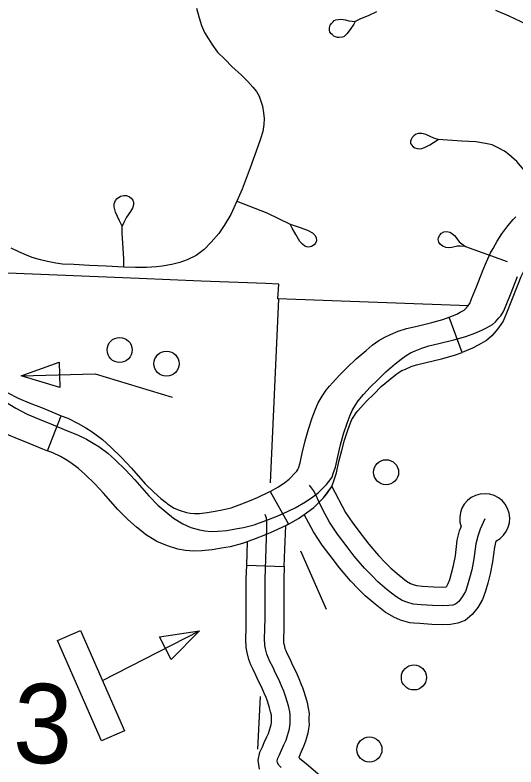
# Model space of a CAD drawing. Extents: x 653372 to 905732, y 627442 to 787275.
# Drawn here: x 658291 to 660290, y 771003 to 774006 of the extents above; entities that cross this region are included whole.
import ezdxf

# ---------------------------------------------------------------- set-up
doc = ezdxf.new("R2010")
doc.units = 0
for name, color, linetype in [('31', 7, 'Continuous'), ('33', 7, 'Continuous'), ('4', 7, 'Continuous'), ('56', 7, 'Continuous'), ('6', 7, 'Continuous')]:
    doc.layers.add(name, color=color, linetype=linetype)

msp = doc.modelspace()

# ---------------------------------------------------------------- linework, layer by layer
at = {"layer": '31'}
for p, q in [((660074.9, 772658.5), (660023, 772799.2)), ((660023, 772799.2), (660023, 772799.2)), ((658420.9, 772265.5), (658475.1, 772405.4)), ((658475.1, 772405.4), (658475.1, 772405.4)), ((659308.4, 772102.8), (659382.7, 771972.5)), ((659215.3, 771808.5), (659365.2, 771803.5))]:
    msp.add_line(p, q, dxfattribs=at)
for points in [[(660023, 772799.2), (660029.7, 772801.7), (660053.3, 772811.3), (660067.6, 772818.7), (660082.9, 772827.3), (660085.2, 772829.5), (660096.6, 772842.3), (660100.6, 772846.9), (660105.2, 772854), (660112.7, 772872), (660132, 772920.1), (660157.6, 772985.9), (660171.7, 773019.9), (660188.5, 773056.1), (660198.5, 773073.8), (660214.2, 773102.8), (660232.8, 773131.9), (660257.5, 773163.2), (660278.4, 773189), (660289.8, 773200)], [(660394.2, 773092.4), (660389.2, 773087.6), (660374.7, 773069.6), (660355.1, 773044.7), (660343.5, 773026.7), (660329.8, 773001.2), (660322, 772987.4), (660309, 772959.5), (660296.7, 772929.9), (660271.5, 772865.1), (660251.6, 772815.2), (660238.4, 772783.7), (660220.7, 772756.3), (660209.2, 772743.2), (660193, 772725), (660172.3, 772705.4), (660138.9, 772686.7), (660116.3, 772675), (660083.9, 772661.8), (660074.9, 772658.5)], [(659170.3, 771953.5), (659201.9, 771959), (659244.8, 771969.9), (659291.2, 771987.2), (659330.5, 772002), (659358, 772014.2), (659408.7, 772038), (659450.4, 772061.8), (659479.3, 772081.7), (659502.2, 772098.6), (659534.2, 772131.1), (659543.4, 772142.2), (659555.7, 772160.5), (659560.9, 772174.7), (659570, 772200.7), (659578.7, 772243.1), (659590.2, 772289.1), (659602.2, 772333), (659616.2, 772375.2), (659627.8, 772407.4), (659635.9, 772426.8), (659647.7, 772446.7), (659660.5, 772465.5), (659681.5, 772490), (659708.5, 772519), (659738.1, 772548.7), (659770.5, 772580.8), (659808.2, 772612.2), (659831.2, 772631.7), (659851.3, 772646), (659869.2, 772656.2), (659887, 772664.2), (659914.4, 772675.6), (659941.8, 772684.4), (659982.1, 772693.8), (660042.2, 772708.5), (660089.2, 772721.8), (660125.3, 772735.1), (660153.3, 772746.5), (660171.7, 772756.1), (660196.1, 772769.8), (660207.6, 772780.6), (660221.4, 772796.2), (660229.1, 772805), (660240.3, 772822.3), (660250.6, 772847), (660270.2, 772896), (660295.6, 772961.3)], [(659545.6, 772523.2), (659557.1, 772536.5), (659585.9, 772567.6), (659616.7, 772598.4), (659651.6, 772632.9), (659691.4, 772666.1), (659716.6, 772687.5), (659742.5, 772706), (659766.8, 772719.7), (659788.7, 772729.6), (659820, 772742.6), (659853.3, 772753.3), (659896.1, 772763.3), (659954.6, 772777.6), (659997.5, 772789.8), (660023, 772799.2)], [(658020.9, 772648.7), (658073.4, 772618.9), (658138.1, 772580.4), (658185.2, 772548.8), (658226.4, 772520.3), (658262.7, 772496.9), (658303.2, 772476.1), (658347.3, 772457.3), (658402.9, 772435), (658456.2, 772412.7), (658475.1, 772405.4)], [(659659.3, 772425.4), (659668.9, 772436.6), (659694, 772463.5), (659722.5, 772492.1), (659752.5, 772521.8), (659788, 772551.4), (659808.8, 772569.1), (659823.1, 772579.3), (659834.6, 772585.7), (659848.4, 772591.9), (659871.8, 772601.7), (659893.4, 772608.6), (659931.1, 772617.5), (659992.9, 772632.6), (660043.9, 772647), (660074.9, 772658.5)], [(657947, 772518.2), (657998.1, 772489.2), (658058, 772453.6), (658100.7, 772424.9), (658143, 772395.6), (658187.6, 772366.9), (658239.5, 772340.1), (658290.1, 772318.7), (658346.1, 772296.2), (658400.2, 772273.6), (658420.9, 772265.5)], [(659308.4, 772102.8), (659342, 772122), (659367.2, 772139.4), (659384.4, 772152.1), (659410.1, 772178.1), (659414.8, 772183.7), (659419.9, 772191.3), (659421.8, 772196.5), (659429, 772217.2), (659437.1, 772256.3), (659449.1, 772304.7), (659461.9, 772351.3), (659476.9, 772396.4), (659489.4, 772431), (659500.1, 772457), (659515.9, 772483.6), (659532.4, 772507.8), (659545.6, 772523.2)], [(658253.2, 772461.3), (658293.7, 772435.3), (658339.8, 772411.5), (658387.2, 772391.4), (658443, 772369), (658496.7, 772346.6), (658539.9, 772329.8), (658575.6, 772312.2), (658602.8, 772296.5), (658624.8, 772282.5), (658660.7, 772256.4), (658690.3, 772228.8), (658731.2, 772189.8), (658768.3, 772149.2), (658824.5, 772085.7), (658861.2, 772048.9), (658892.4, 772021.3), (658923.8, 771996.1), (658959.9, 771973.7), (658993, 771959.4), (659026.3, 771949.3), (659048.6, 771945.5), (659073.5, 771943.6), (659100.2, 771943.9), (659136, 771947.6), (659170.3, 771953.5)], [(659382.7, 771972.5), (659421.9, 771994.9), (659454.4, 772017.3), (659482.9, 772038.4), (659521.4, 772077.3), (659535.1, 772093.8), (659554.5, 772122.7), (659563.1, 772146), (659573.9, 772177.3), (659583.3, 772223), (659594.3, 772266.7), (659605.5, 772307.8), (659618.6, 772347.2), (659629.3, 772376.9), (659634.7, 772389.8), (659642.5, 772403), (659651.6, 772416.4), (659659.4, 772425.4)], [(658475.1, 772405.4), (658501.6, 772395.1), (658542.4, 772375), (658573.2, 772357.2), (658598.5, 772341.1), (658640, 772310.9), (658673.3, 772280), (658716.3, 772238.9), (658755.6, 772196), (658810.7, 772133.7), (658844.2, 772100.1), (658872.2, 772075.2), (658894.9, 772057.1)], [(658801, 771940.1), (658775.5, 771960.5), (658741.3, 771990.9), (658701.3, 772030.9), (658644.1, 772095.6), (658609.1, 772133.8), (658570.3, 772170.9), (658544.5, 772195), (658514, 772217.1), (658495.4, 772228.9), (658471.7, 772242.6), (658441.2, 772257.7), (658420.9, 772265.5)], [(659881.7, 771577.6), (659865.9, 771579), (659829.7, 771589.4), (659802.3, 771600.6), (659767.8, 771621), (659728.2, 771652.6), (659687.9, 771686.7), (659662, 771713), (659629.4, 771746.3), (659586, 771798.2), (659556.5, 771836.5), (659516.9, 771888.7), (659481.4, 771941.9), (659444.7, 772010.6), (659482.9, 772038.4), (659521.4, 772077.3), (659554.7, 772123.1)], [(660165.2, 771994.2), (660146.8, 771952.2), (660137.1, 771924.1), (660129.7, 771894.2), (660122, 771834.1), (660113.6, 771790.6), (660104.9, 771756.6), (660096.9, 771728.5), (660087.9, 771703.6), (660075.5, 771682.1), (660061.3, 771664.2), (660048.6, 771653.3), (660038.4, 771649.5), (660021.8, 771647), (659996.4, 771646), (659957.4, 771647.2), (659911.4, 771650.3), (659879.6, 771653.1), (659854.4, 771660.3), (659835.7, 771668), (659810.4, 771682.9), (659775.8, 771710.6), (659738.9, 771741.8), (659715.4, 771765.6), (659685, 771796.6), (659644.6, 771845.1), (659616.1, 771882), (659578, 771932.2), (659545.8, 771980.5), (659519.5, 772029.7), (659503.4, 772062.7), (659490.6, 772089.7), (659481.7, 772107.1), (659465.7, 772127.7)], [(659554.7, 772123.1), (659610.2, 772019.1), (659639.2, 771975.8), (659675.7, 771927.6), (659703.1, 771892.1), (659740.7, 771847), (659768.9, 771818.2), (659789.9, 771796.9), (659823.5, 771768.5), (659853.1, 771744.8), (659869.2, 771735.3), (659879.1, 771731.3), (659893.3, 771727.2), (659894.5, 771727.1)], [(658894.9, 772057.1), (658898.7, 772054), (658926.2, 772036.9), (658950.3, 772026.5), (658975.1, 772019), (658989.2, 772016.6), (659007.4, 772015.2), (659027.4, 772015.4), (659057.3, 772018.5), (659089.1, 772024), (659117.7, 772029), (659153.9, 772038.2), (659196.4, 772054), (659233.6, 772068), (659258.3, 772079), (659305.6, 772101.2), (659308.4, 772102.8)], [(659353.3, 771000.3), (659343.7, 771010.5), (659338.2, 771019.6), (659337.1, 771027.7), (659339.2, 771038), (659345.9, 771051.7), (659353.6, 771069.3), (659363.7, 771091.5), (659372.3, 771110.5), (659377.8, 771128.3), (659381.7, 771141.2), (659385.8, 771155), (659387.9, 771167), (659389.1, 771176), (659388.9, 771185.8), (659388.8, 771198.4), (659389.2, 771211.4), (659387.4, 771223.6), (659383.4, 771242.1), (659377.7, 771260.8), (659370.4, 771285.3), (659362.9, 771306.1), (659354.6, 771327), (659343.2, 771352.5), (659330.5, 771377.5), (659319.6, 771402.1), (659308.2, 771424.4), (659301.5, 771439.4), (659296.1, 771453.9), (659290.9, 771475.2), (659288.2, 771489.6), (659286.6, 771513.9), (659287.9, 771554.8), (659288.7, 771598.8), (659288.6, 771654.9), (659288.4, 771706), (659288.5, 771753.1), (659292.6, 771874.8), (659295.5, 771957.7), (659296.3, 771984.1), (659294.9, 771996.7), (659289.5, 772010.8)], [(659382.7, 771972.5), (659374.8, 771968), (659320.6, 771942.6), (659290.5, 771929.2), (659249, 771913.6), (659198.8, 771894.8), (659149.1, 771882.2), (659114.5, 771876.2), (659077.8, 771869.9), (659036, 771865.5), (659002.7, 771865.2), (658970.9, 771867.5), (658940.5, 771872.8), (658898.7, 771885.4), (658856.6, 771903.6), (658811.9, 771931.3), (658801, 771940.1)], [(659365.2, 771803.5), (659367.5, 771872.2), (659370.8, 771966.1)], [(659894.5, 771727.1), (659917.2, 771725.1), (659961.1, 771722.1), (659996, 771721.1), (660011.2, 771721.7), (660013.3, 771724.3), (660019.7, 771735.4), (660025.5, 771751.4), (660032.4, 771776.1), (660040.4, 771807), (660047.9, 771846), (660055.8, 771908), (660065.1, 771945.4), (660070.7, 771961.5)], [(659215.3, 771808.5), (659218.4, 771902.2)], [(660209.5, 771904.5), (660203.5, 771880.3), (660196.1, 771822.2), (660186.8, 771774.2), (660177.3, 771737.1), (660168.4, 771705.5), (660156.2, 771671.7), (660137.7, 771639.8), (660115.6, 771611.9), (660087.3, 771587.8), (660057.4, 771576.5), (660028.8, 771572.2), (659996.7, 771571), (659953.7, 771572.3), (659905.7, 771575.6), (659881.7, 771577.6)], [(659296.5, 771269), (659292.8, 771279.6), (659285.5, 771297.8), (659275.5, 771320.2), (659262.8, 771345.3), (659251.9, 771369.7), (659240.5, 771392), (659232, 771411), (659224.2, 771431.9), (659217.5, 771459.4), (659213.6, 771480.4), (659211.6, 771512.7), (659212.9, 771556.7), (659213.7, 771599.4), (659213.6, 771654.6), (659213.4, 771705.9), (659213.5, 771754.4), (659215.3, 771808.5)], [(659365.2, 771803.5), (659363.4, 771751.8), (659363.4, 771706.1), (659363.6, 771655.1), (659363.8, 771598.1), (659362.9, 771553), (659361.7, 771515.1), (659362.7, 771498.9), (659364.2, 771491), (659367.9, 771476), (659370.9, 771467.9), (659375.8, 771456.9), (659387.3, 771434.5), (659398.3, 771409.8), (659411, 771384.7), (659423.7, 771356.2), (659433.1, 771332.7), (659437.8, 771319.5)], [(659437.8, 771319.5), (659441.7, 771308.7), (659449.5, 771282.5), (659456.1, 771260.8), (659461.2, 771237.1), (659464.4, 771216), (659463.9, 771197.5), (659463.9, 771186.6), (659464.1, 771171.7), (659462, 771155.6), (659458.9, 771137.9), (659453.6, 771119.7), (659449.5, 771106.2), (659442.6, 771083.9), (659431.9, 771060.4), (659422.9, 771040.5), (659425.5, 771038.4), (659454.4, 771015.5), (659499.1, 770976.1), (659527.5, 770947.9), (659566.6, 770908.2), (659619.9, 770852.2)], [(659266, 770994), (659261, 771030.3), (659267.6, 771062.3), (659277.8, 771083.1), (659285.1, 771099.9), (659295.4, 771122.5), (659302, 771137.1), (659306.1, 771150.4), (659309.9, 771162.7), (659312.6, 771172.1), (659313.8, 771178.5), (659314, 771180.2), (659313.9, 771185), (659313.8, 771199.3), (659314.1, 771206.8), (659313.6, 771210), (659310.7, 771223.3), (659305.9, 771239.1), (659299.1, 771261.9), (659296.5, 771269)]]:
    msp.add_lwpolyline(points, dxfattribs=at)
msp.add_arc((660165.2, 771994.2), 100, 296.308, 199.0581, dxfattribs=at)
at = {"layer": '33'}
for points in [[(659015.4, 774032.7), (659025.4, 773994.8), (659035.1, 773964.1), (659047.1, 773936.1), (659062.2, 773910.5), (659076.6, 773889.2), (659099.1, 773857.4), (659129.9, 773827.8), (659156, 773800), (659194.2, 773765.4), (659219.2, 773740.1), (659239.7, 773717.2), (659253.8, 773700.3), (659265.5, 773681.2), (659272, 773661.7), (659278.4, 773641.9), (659282.3, 773615.4), (659284.6, 773593), (659283.3, 773568.4), (659279.5, 773541), (659271, 773511.4), (659260.1, 773480), (659228.8, 773394.8), (659197, 773310.5), (659175.6, 773262.5), (659151.7, 773209.3), (659125.8, 773164.9), (659103.7, 773132.7), (659073.9, 773097.9), (659045, 773069.4), (659013.2, 773045.1), (658978, 773027.4), (658949, 773017.2), (658916.2, 773008.8), (658878.5, 773002.9), (658855.6, 772999.5), (658815.1, 772997.8), (658771.7, 772997.9), (658724.8, 772998.7), (658654, 773002.6), (658587.9, 773005.8), (658525.3, 773008.8), (658479.6, 773010.8), (658453.2, 773014.5), (658420.6, 773021.9), (658392.1, 773028.1), (658359.5, 773037.2)], [(659733.2, 774018.6), (659700.5, 774002.8), (659670, 773990), (659648.8, 773980.2)], [(660650.4, 773748.4), (660618.5, 773755.6), (660592.2, 773764.4), (660575.3, 773775), (660539.5, 773799.7), (660509, 773825.1), (660483.1, 773846.8), (660447.7, 773882.4), (660425.9, 773904.7), (660405.6, 773922.9), (660375.7, 773945.1), (660348.1, 773960.4), (660308.1, 773979.7), (660262.2, 774000.7), (660209.5, 774024)], [(659648.8, 773980.2), (659642.5, 773969.2), (659628.2, 773947.5), (659614.8, 773931.1), (659604.1, 773920.5), (659597.2, 773917.5), (659584.7, 773915.5), (659577, 773915.7), (659570.3, 773917.9), (659563.6, 773921), (659556.5, 773927.2), (659550.6, 773932.2), (659547.6, 773938.3), (659545.4, 773944.4), (659546.1, 773954.4), (659548.4, 773964.8), (659553.1, 773972.3), (659559.7, 773978.9), (659564.6, 773984), (659571.6, 773987), (659580.4, 773988.3), (659590.5, 773988.8), (659609.3, 773986.2), (659623.2, 773983), (659636.8, 773981.4), (659648.8, 773980.2)], [(659978.9, 773508), (659962.1, 773513.6), (659929.6, 773528), (659920.8, 773530.9), (659913.7, 773532.2), (659907.5, 773532.4), (659900.3, 773532), (659895.1, 773530.8), (659888.7, 773528.4), (659882.9, 773523.7), (659876.1, 773517), (659871.9, 773509.2), (659869.6, 773501.5), (659869.6, 773492.3), (659873.2, 773486.8), (659879, 773479.8), (659886.3, 773474.7), (659895.9, 773472.7), (659905.6, 773471.8), (659914.2, 773472.7), (659925.1, 773476.3), (659946.1, 773487.7), (659960.1, 773496.2), (659978.9, 773508)], [(660446.2, 773232.4), (660406.8, 773282.9), (660351.7, 773352.1), (660293.7, 773421.3), (660262, 773449.1), (660244.6, 773462.3), (660216.5, 773476.8), (660195.1, 773486.6), (660168.4, 773493.1), (660130.2, 773498.9), (660074.3, 773502.3), (659978.9, 773508)], [(658718.1, 773162.5), (658707.5, 773184), (658691.8, 773218.3), (658686.2, 773240.1), (658686.7, 773252.2), (658691.9, 773265.2), (658698.9, 773273.1), (658712.2, 773281.7), (658724.4, 773284.9), (658736.1, 773284.6), (658748.2, 773279.7), (658754.3, 773274.1), (658760.4, 773265.8), (658763.3, 773258.1), (658763.9, 773247.2), (658759.9, 773234.3), (658751.3, 773220.6), (658735.8, 773198.1), (658724.4, 773177.2), (658718.1, 773162.5)], [(659175.6, 773262.5), (659296.3, 773215.9), (659389.1, 773170.8)], [(658724.8, 772998.7), (658725.4, 773032.1), (658721, 773094.4), (658718.1, 773134.2), (658718.1, 773162.5)], [(659389.1, 773170.8), (659425.2, 773158.4), (659458.2, 773146.6), (659477.6, 773135.7), (659487.7, 773126.4), (659491.9, 773117), (659493.3, 773103.8), (659490.4, 773094.7), (659483.9, 773087.3), (659474.2, 773081.7), (659463.8, 773078.9), (659455.7, 773079.6), (659447.2, 773082.1), (659437.6, 773090.5), (659427.5, 773100.7), (659410.8, 773129.1), (659397.1, 773154.3), (659389.1, 773170.8)], [(660088.9, 773081.1), (660067.8, 773082.9), (660056.3, 773082.1), (660034.5, 773077.6), (660020.1, 773075.8), (660009.3, 773076.7), (659997.4, 773082.2), (659988.5, 773089.3), (659981.4, 773098.7), (659979.4, 773109), (659980.8, 773117), (659985.6, 773126), (659992.1, 773134.4), (660002, 773139.8), (660014.1, 773140.6), (660025.4, 773138), (660032.7, 773134.3), (660043.9, 773125.4), (660053.3, 773113.7), (660063.8, 773100.2), (660073.8, 773091.3), (660088.9, 773081.1)], [(658359.5, 773037.2), (658336.4, 773046.2), (658306.3, 773060), (658275.7, 773074.4)], [(660088.9, 773081.1), (660255.3, 773021.8)]]:
    msp.add_lwpolyline(points, dxfattribs=at)
at = {"layer": '4'}
for points in [[(659342.6, 772872.2), (659308.4, 772136.9)], [(659268.6, 771284.4), (659258.8, 771074)]]:
    msp.add_lwpolyline(points, dxfattribs=at)
at = {"layer": '56'}
for p, q in [((658314.9, 772565.2), (658466.7, 772619.8)), ((658466.7, 772619.8), (658469.1, 772517.8)), ((658469.1, 772517.8), (658314.9, 772565.2)), ((658867.7, 771522.4), (659027.1, 771547.1)), ((658914.4, 771431.7), (658867.7, 771522.4)), ((659027.1, 771547.1), (658914.4, 771431.7))]:
    msp.add_line(p, q, dxfattribs=at)
for points in [[(658314.9, 772565.2), (658610.7, 772572.1), (658918.3, 772479.3)], [(659429.9, 771866.5), (659532.3, 771633.5)], [(658640, 771347.7), (659027.1, 771547.1)]]:
    msp.add_lwpolyline(points, dxfattribs=at)
msp.add_lwpolyline([(658460.4, 771507.7), (658551.9, 771548), (658728, 771147.5), (658636.5, 771107.2)], close=True, dxfattribs=at)
for centre in [(658708.2, 772668.1), (658895.3, 772613.2), (659771.6, 772179.7), (659882.4, 771360.2), (659705.1, 771072.5)]:
    msp.add_circle(centre, 50, dxfattribs=at)
at = {"layer": '6'}
msp.add_lwpolyline([(660101.1, 772844.1), (660027.5, 772846.8), (659340, 772872.3), (659343, 772930.8), (659291, 772932.9), (659034, 772943), (658786, 772952.8), (658032, 772984.1), (658019.4, 772984.6), (657531.3, 773002.1), (657438.7, 773006.5), (657438.9, 772990), (657436.5, 772916.5), (657385.4, 772920), (657145.3, 772929.7), (657030.4, 772936.4), (656985.9, 772982.1), (656959.4, 773016.2), (656909.8, 773079.7), (656733.6, 773308.5), (656639.5, 773437.5), (656521, 773414.8)], dxfattribs=at)

# ---------------------------------------------------------------- texts
at = {"layer": '56'}
msp.add_text('3', height=316.8, rotation=358.28, dxfattribs=at).set_placement((658279.9, 771021.5))

doc.saveas('drawing.dxf')
